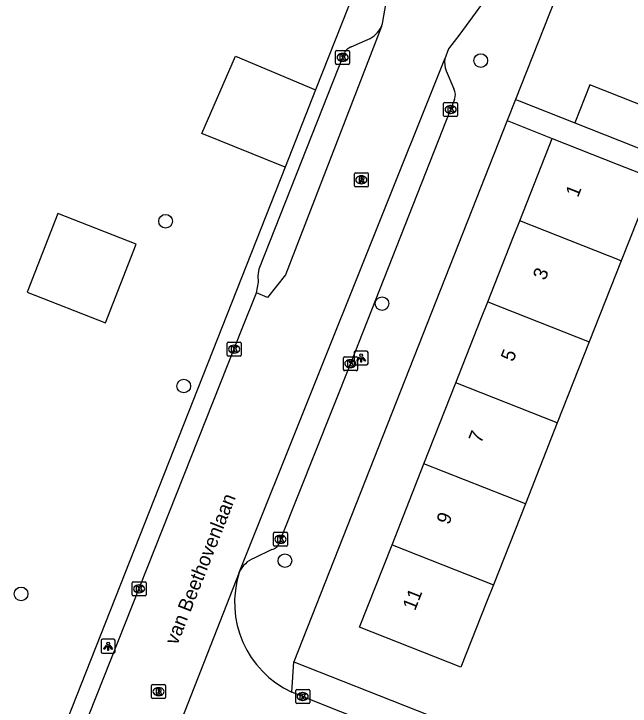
# Model space of a CAD drawing. Extents: x 159822 to 160765, y 380693 to 381634.
# Drawn here: x 160308.25 to 160352.4, y 381326.15 to 381375.72 of the extents above; entities that cross this region are included whole.
import ezdxf

# ---------------------------------------------------------------- set-up
doc = ezdxf.new("R2010")
doc.units = 0
for name, color, linetype in [('IMGEO_Boom', 7, 'Continuous'), ('IMGEO_Groenvoorziening', 7, 'Continuous'), ('IMGEO_Kolk', 7, 'Continuous'), ('IMGEO_Lichtpunt', 7, 'Continuous'), ('IMGEO_Openbare_ruimte_label', 7, 'Continuous'), ('IMGEO_Pand', 7, 'Continuous'), ('IMGEO_Pand_nummerreeks', 7, 'Continuous'), ('IMGEO_Rijbaan_lokaal_open', 7, 'Continuous'), ('IMGEO_Rioolput', 7, 'Continuous'), ('IMGEO_Voetpad_open', 7, 'Continuous')]:
    doc.layers.add(name, color=color, linetype=linetype)

msp = doc.modelspace()

# ---------------------------------------------------------------- linework, layer by layer
at = {"layer": 'IMGEO_Boom'}
for centre in [(160341.698, 381372.378), (160319.125, 381360.871), (160334.627, 381354.969), (160320.428, 381349.072), (160327.669, 381336.566), (160308.778, 381334.183)]:
    msp.add_circle(centre, 0.489, dxfattribs=at)
at = {"layer": 'IMGEO_Groenvoorziening'}
for points in [[(160327.681, 381364.751), (160321.709, 381367.163), (160324.123, 381372.682), (160329.863, 381370.275)], [(160317.018, 381359.223), (160311.413, 381361.421), (160309.209, 381355.803), (160314.814, 381353.604), (160317.018, 381359.223)]]:
    msp.add_lwpolyline(points, dxfattribs=at)
at = {"layer": 'IMGEO_Kolk'}
for p, q in [((160331.378, 381373.104), (160332.23, 381373.104)), ((160331.303, 381372.178), (160331.303, 381373.03)), ((160331.791, 381372.884), (160331.816, 381372.884)), ((160332.304, 381373.03), (160332.304, 381372.178)), ((160332.23, 381372.104), (160331.378, 381372.104)), ((160331.814, 381372.324), (160331.789, 381372.324)), ((160339.041, 381368.445), (160339.041, 381369.297)), ((160339.116, 381369.371), (160339.968, 381369.371)), ((160339.529, 381369.151), (160339.554, 381369.151)), ((160340.042, 381369.297), (160340.042, 381368.445)), ((160339.968, 381368.371), (160339.116, 381368.371)), ((160339.552, 381368.591), (160339.527, 381368.591)), ((160323.536, 381351.281), (160323.536, 381352.133)), ((160323.611, 381352.207), (160324.463, 381352.207)), ((160324.024, 381351.987), (160324.049, 381351.987)), ((160324.537, 381352.133), (160324.537, 381351.281)), ((160324.047, 381351.427), (160324.022, 381351.427)), ((160324.463, 381351.207), (160323.611, 381351.207)), ((160331.859, 381350.245), (160331.859, 381351.097)), ((160331.934, 381351.171), (160332.786, 381351.171)), ((160332.347, 381350.951), (160332.372, 381350.951)), ((160332.86, 381351.097), (160332.86, 381350.245)), ((160332.37, 381350.391), (160332.345, 381350.391)), ((160332.786, 381350.171), (160331.934, 381350.171)), ((160326.855, 381337.67), (160326.855, 381338.522)), ((160326.93, 381338.596), (160327.782, 381338.596)), ((160327.343, 381338.376), (160327.368, 381338.376)), ((160327.856, 381338.522), (160327.856, 381337.67)), ((160327.782, 381337.596), (160326.93, 381337.596)), ((160327.366, 381337.816), (160327.341, 381337.816)), ((160316.727, 381334.121), (160316.727, 381334.973)), ((160316.802, 381335.047), (160317.654, 381335.047)), ((160317.728, 381334.973), (160317.728, 381334.121)), ((160317.215, 381334.827), (160317.24, 381334.827)), ((160317.654, 381334.047), (160316.802, 381334.047)), ((160317.238, 381334.267), (160317.213, 381334.267)), ((160328.447, 381326.411), (160328.447, 381327.263)), ((160328.522, 381327.337), (160329.374, 381327.337)), ((160328.935, 381327.117), (160328.96, 381327.117)), ((160329.448, 381327.263), (160329.448, 381326.411)), ((160328.958, 381326.557), (160328.933, 381326.557)), ((160329.374, 381326.337), (160328.522, 381326.337))]:
    msp.add_line(p, q, dxfattribs=at)
for points in [[(160331.378, 381373.104), (160332.23, 381373.104)], [(160331.303, 381372.178), (160331.303, 381373.03)], [(160331.624, 381372.804), (160331.747, 381372.804), (160331.747, 381372.653), (160331.877, 381372.804), (160332.041, 381372.804), (160331.895, 381372.653), (160332.048, 381372.404), (160331.896, 381372.404), (160331.811, 381372.568), (160331.747, 381372.501), (160331.747, 381372.404), (160331.624, 381372.404), (160331.624, 381372.804)], [(160332.304, 381373.03), (160332.304, 381372.178)], [(160332.23, 381372.104), (160331.378, 381372.104)], [(160339.041, 381368.445), (160339.041, 381369.297)], [(160339.116, 381369.371), (160339.968, 381369.371)], [(160340.042, 381369.297), (160340.042, 381368.445)], [(160339.362, 381369.071), (160339.485, 381369.071), (160339.485, 381368.92), (160339.615, 381369.071), (160339.779, 381369.071), (160339.633, 381368.92), (160339.786, 381368.671), (160339.634, 381368.671), (160339.549, 381368.835), (160339.485, 381368.768), (160339.485, 381368.671), (160339.362, 381368.671), (160339.362, 381369.071)], [(160339.968, 381368.371), (160339.116, 381368.371)], [(160323.536, 381351.281), (160323.536, 381352.133)], [(160323.611, 381352.207), (160324.463, 381352.207)], [(160323.857, 381351.907), (160323.98, 381351.907), (160323.98, 381351.756), (160324.11, 381351.907), (160324.274, 381351.907), (160324.128, 381351.756), (160324.281, 381351.507), (160324.129, 381351.507), (160324.044, 381351.671), (160323.98, 381351.604), (160323.98, 381351.507), (160323.857, 381351.507), (160323.857, 381351.907)], [(160324.537, 381352.133), (160324.537, 381351.281)], [(160324.463, 381351.207), (160323.611, 381351.207)], [(160331.859, 381350.245), (160331.859, 381351.097)], [(160331.934, 381351.171), (160332.786, 381351.171)], [(160332.18, 381350.871), (160332.303, 381350.871), (160332.303, 381350.72), (160332.433, 381350.871), (160332.597, 381350.871), (160332.451, 381350.72), (160332.604, 381350.471), (160332.452, 381350.471), (160332.367, 381350.635), (160332.303, 381350.568), (160332.303, 381350.471), (160332.18, 381350.471), (160332.18, 381350.871)], [(160332.86, 381351.097), (160332.86, 381350.245)], [(160332.786, 381350.171), (160331.934, 381350.171)], [(160326.855, 381337.67), (160326.855, 381338.522)], [(160326.93, 381338.596), (160327.782, 381338.596)], [(160327.856, 381338.522), (160327.856, 381337.67)], [(160327.176, 381338.296), (160327.299, 381338.296), (160327.299, 381338.145), (160327.429, 381338.296), (160327.593, 381338.296), (160327.447, 381338.145), (160327.6, 381337.896), (160327.448, 381337.896), (160327.363, 381338.06), (160327.299, 381337.993), (160327.299, 381337.896), (160327.176, 381337.896), (160327.176, 381338.296)], [(160327.782, 381337.596), (160326.93, 381337.596)], [(160316.727, 381334.121), (160316.727, 381334.973)], [(160316.802, 381335.047), (160317.654, 381335.047)], [(160317.728, 381334.973), (160317.728, 381334.121)], [(160317.048, 381334.747), (160317.171, 381334.747), (160317.171, 381334.596), (160317.301, 381334.747), (160317.465, 381334.747), (160317.319, 381334.596), (160317.472, 381334.347), (160317.32, 381334.347), (160317.235, 381334.511), (160317.171, 381334.444), (160317.171, 381334.347), (160317.048, 381334.347), (160317.048, 381334.747)], [(160317.654, 381334.047), (160316.802, 381334.047)], [(160328.447, 381326.411), (160328.447, 381327.263)], [(160328.522, 381327.337), (160329.374, 381327.337)], [(160328.768, 381327.037), (160328.891, 381327.037), (160328.891, 381326.886), (160329.021, 381327.037), (160329.185, 381327.037), (160329.039, 381326.886), (160329.192, 381326.637), (160329.04, 381326.637), (160328.955, 381326.801), (160328.891, 381326.734), (160328.891, 381326.637), (160328.768, 381326.637), (160328.768, 381327.037)], [(160329.448, 381327.263), (160329.448, 381326.411)], [(160329.374, 381326.337), (160328.522, 381326.337)]]:
    msp.add_lwpolyline(points, dxfattribs=at)
for centre, start, end in [((160331.38, 381373.028), 91.552, 178.448), ((160331.38, 381373.028), 91.552, 178.448), ((160332.228, 381373.028), 1.552, 88.448), ((160332.228, 381373.028), 1.552, 88.448), ((160331.38, 381372.18), 181.552, 268.448), ((160331.38, 381372.18), 181.552, 268.448), ((160332.228, 381372.18), 271.552, 358.448), ((160332.228, 381372.18), 271.552, 358.448), ((160339.118, 381369.295), 91.552, 178.448), ((160339.118, 381369.295), 91.552, 178.448), ((160339.966, 381369.295), 1.552, 88.448), ((160339.966, 381369.295), 1.552, 88.448), ((160339.118, 381368.447), 181.552, 268.448), ((160339.118, 381368.447), 181.552, 268.448), ((160339.966, 381368.447), 271.552, 358.448), ((160339.966, 381368.447), 271.552, 358.448), ((160323.613, 381352.131), 91.552, 178.448), ((160323.613, 381352.131), 91.552, 178.448), ((160324.461, 381352.131), 1.552, 88.448), ((160324.461, 381352.131), 1.552, 88.448), ((160323.613, 381351.283), 181.552, 268.448), ((160323.613, 381351.283), 181.552, 268.448), ((160324.461, 381351.283), 271.552, 358.448), ((160324.461, 381351.283), 271.552, 358.448), ((160331.936, 381351.095), 91.552, 178.448), ((160331.936, 381351.095), 91.552, 178.448), ((160332.784, 381351.095), 1.552, 88.448), ((160332.784, 381351.095), 1.552, 88.448), ((160331.936, 381350.247), 181.552, 268.448), ((160331.936, 381350.247), 181.552, 268.448), ((160332.784, 381350.247), 271.552, 358.448), ((160332.784, 381350.247), 271.552, 358.448), ((160326.932, 381338.52), 91.552, 178.448), ((160326.932, 381338.52), 91.552, 178.448), ((160327.78, 381338.52), 1.552, 88.448), ((160327.78, 381338.52), 1.552, 88.448), ((160326.932, 381337.672), 181.552, 268.448), ((160326.932, 381337.672), 181.552, 268.448), ((160327.78, 381337.672), 271.552, 358.448), ((160327.78, 381337.672), 271.552, 358.448), ((160316.804, 381334.971), 91.552, 178.448), ((160316.804, 381334.971), 91.552, 178.448), ((160317.652, 381334.971), 1.552, 88.448), ((160317.652, 381334.971), 1.552, 88.448), ((160316.804, 381334.123), 181.552, 268.448), ((160316.804, 381334.123), 181.552, 268.448), ((160317.652, 381334.123), 271.552, 358.448), ((160317.652, 381334.123), 271.552, 358.448), ((160328.524, 381327.261), 91.552, 178.448), ((160328.524, 381327.261), 91.552, 178.448), ((160329.372, 381327.261), 1.552, 88.448), ((160329.372, 381327.261), 1.552, 88.448), ((160328.524, 381326.413), 181.552, 268.448), ((160328.524, 381326.413), 181.552, 268.448), ((160329.372, 381326.413), 271.552, 358.448), ((160329.372, 381326.413), 271.552, 358.448)]:
    msp.add_arc(centre, 0.0765, start, end, dxfattribs=at)
for centre, major_axis, ratio, start_param, end_param in [((160331.79, 381372.604), (-0.387, 0.002), 0.722429, 4.712389, 7.853982), ((160331.815, 381372.604), (-0.39, 0.002), 0.717154, 1.570796, 4.712389), ((160339.528, 381368.871), (-0.387, 0.002), 0.722429, 4.712389, 7.853982), ((160339.553, 381368.871), (-0.39, 0.002), 0.717154, 1.570796, 4.712389), ((160324.023, 381351.707), (-0.387, 0.002), 0.722429, 4.712389, 7.853982), ((160324.048, 381351.707), (-0.39, 0.002), 0.717154, 1.570796, 4.712389), ((160332.346, 381350.671), (-0.387, 0.002), 0.722429, 4.712389, 7.853982), ((160332.371, 381350.671), (-0.39, 0.002), 0.717154, 1.570796, 4.712389), ((160327.342, 381338.096), (-0.387, 0.002), 0.722429, 4.712389, 7.853982), ((160327.367, 381338.096), (-0.39, 0.002), 0.717154, 1.570796, 4.712389), ((160317.214, 381334.547), (-0.387, 0.002), 0.722429, 4.712389, 7.853982), ((160317.239, 381334.547), (-0.39, 0.002), 0.717154, 1.570796, 4.712389), ((160328.934, 381326.837), (-0.387, 0.002), 0.722429, 4.712389, 7.853982), ((160328.959, 381326.837), (-0.39, 0.002), 0.717154, 1.570796, 4.712389)]:
    msp.add_ellipse(centre, major_axis=major_axis, ratio=ratio, start_param=start_param, end_param=end_param, dxfattribs=at)
at = {"layer": 'IMGEO_Lichtpunt'}
for p, q in [((160332.628, 381351.48), (160332.628, 381350.673)), ((160332.628, 381351.48), (160332.628, 381350.673)), ((160333.53, 381351.575), (160332.722, 381351.575)), ((160333.53, 381351.575), (160332.722, 381351.575)), ((160333.624, 381350.673), (160333.624, 381351.48)), ((160333.624, 381350.673), (160333.624, 381351.48)), ((160332.722, 381350.579), (160333.53, 381350.579)), ((160332.722, 381350.579), (160333.53, 381350.579)), ((160315.41, 381330.938), (160314.602, 381330.938)), ((160315.41, 381330.938), (160314.602, 381330.938)), ((160314.508, 381330.843), (160314.508, 381330.036)), ((160314.508, 381330.843), (160314.508, 381330.036)), ((160315.504, 381330.036), (160315.504, 381330.843)), ((160315.504, 381330.036), (160315.504, 381330.843)), ((160314.602, 381329.942), (160315.41, 381329.942)), ((160314.602, 381329.942), (160315.41, 381329.942))]:
    msp.add_line(p, q, dxfattribs=at)
for points in [[(160333.002, 381351.144), (160333.041, 381351.116), (160332.853, 381350.854), (160332.815, 381350.881), (160333.002, 381351.144)], [(160333.104, 381351.096), (160333.151, 381351.096), (160333.151, 381350.774), (160333.104, 381350.774), (160333.104, 381351.096)], [(160333.214, 381351.116), (160333.252, 381351.143), (160333.439, 381350.881), (160333.4, 381350.853), (160333.214, 381351.116)], [(160314.882, 381330.507), (160314.921, 381330.479), (160314.733, 381330.217), (160314.695, 381330.244), (160314.882, 381330.507)], [(160314.984, 381330.459), (160315.031, 381330.459), (160315.031, 381330.137), (160314.984, 381330.137), (160314.984, 381330.459)], [(160315.094, 381330.479), (160315.132, 381330.506), (160315.319, 381330.244), (160315.28, 381330.216), (160315.094, 381330.479)]]:
    msp.add_lwpolyline(points, dxfattribs=at)
for centre in [(160333.127, 381351.278), (160315.007, 381330.641)]:
    msp.add_circle(centre, 0.0994, dxfattribs=at)
for centre, start, end in [((160332.722, 381351.48), 90, 180), ((160332.722, 381351.48), 90, 180), ((160333.53, 381351.48), 0, 90), ((160333.53, 381351.48), 0, 90), ((160332.722, 381350.673), 180, 270), ((160332.722, 381350.673), 180, 270), ((160333.53, 381350.673), 270, 0), ((160333.53, 381350.673), 270, 360), ((160314.602, 381330.843), 90, 180), ((160314.602, 381330.843), 90, 180), ((160315.41, 381330.843), 0, 90), ((160315.41, 381330.843), 0, 90), ((160314.602, 381330.036), 180, 270), ((160314.602, 381330.036), 180, 270), ((160315.41, 381330.036), 270, 0), ((160315.41, 381330.036), 270, 360)]:
    msp.add_arc(centre, 0.0946, start, end, dxfattribs=at)
at = {"layer": 'IMGEO_Pand'}
for points in [[(160354.051, 381365.707), (160355.121, 381368.421), (160352.707, 381369.373), (160349.51, 381370.633), (160348.44, 381367.919)], [(160348.44, 381367.919), (160351.637, 381366.659), (160354.051, 381365.707)], [(160344.492, 381360.891), (160346.823, 381366.8)], [(160346.823, 381366.8), (160351.475, 381364.966), (160354.086, 381363.936)], [(160354.086, 381363.936), (160351.755, 381358.026)], [(160342.206, 381355.094), (160344.003, 381359.651), (160344.492, 381360.891)], [(160351.755, 381358.026), (160344.492, 381360.891)], [(160351.755, 381358.026), (160349.468, 381352.229)], [(160339.92, 381349.298), (160341.716, 381353.853), (160342.206, 381355.094)], [(160342.206, 381355.094), (160349.468, 381352.229)], [(160349.468, 381352.229), (160347.182, 381346.432)], [(160337.633, 381343.501), (160339.92, 381349.298)], [(160347.182, 381346.432), (160339.92, 381349.298)], [(160347.182, 381346.432), (160344.895, 381340.635)], [(160335.347, 381337.705), (160337.633, 381343.501)], [(160344.895, 381340.635), (160337.633, 381343.501)], [(160344.895, 381340.635), (160342.609, 381334.838)], [(160342.609, 381334.838), (160342.114, 381333.583), (160340.279, 381328.931), (160333.016, 381331.796), (160335.347, 381337.705)], [(160335.347, 381337.705), (160342.609, 381334.838)]]:
    msp.add_lwpolyline(points, dxfattribs=at)
at = {"layer": 'IMGEO_Rijbaan_lokaal_open'}
for points in [[(160334.58, 381374.806), (160334.664, 381375.02), (160335.694, 381380.931), (160335.886, 381381.655), (160336.806, 381383.995), (160337.727, 381386.312), (160338.069, 381386.973), (160341.463, 381391.931)], [(160346.086, 381390.314), (160345.23, 381383.344), (160343.412, 381378.689), (160342.853, 381377.914), (160340.19, 381374.267), (160339.393, 381373.215), (160339.132, 381372.508)], [(160334.58, 381374.806), (160327.725, 381357.024), (160326.426, 381355.415), (160325.632, 381355.733)], [(160324.406, 381335.726), (160339.132, 381372.508)], [(160311.054, 381318.986), (160324.621, 381353.178), (160325.632, 381355.733)], [(160324.406, 381335.726), (160317.046, 381316.965), (160316.946, 381316.648)], [(160341.019, 381322.049), (160330.297, 381326.294), (160328.162, 381327.153)]]:
    msp.add_lwpolyline(points, dxfattribs=at)
msp.add_arc((160331.129, 381333.562), 7.063, 162.1595, 245.1589, dxfattribs=at)
at = {"layer": 'IMGEO_Rioolput'}
for p, q in [((160332.646, 381363.414), (160332.646, 381364.266)), ((160332.721, 381364.34), (160333.573, 381364.34)), ((160333.647, 381364.266), (160333.647, 381363.414)), ((160333.134, 381364.12), (160333.159, 381364.12)), ((160333.573, 381363.34), (160332.721, 381363.34)), ((160333.157, 381363.56), (160333.132, 381363.56)), ((160318.121, 381326.764), (160318.121, 381327.616)), ((160318.196, 381327.69), (160319.048, 381327.69)), ((160318.609, 381327.47), (160318.634, 381327.47)), ((160319.122, 381327.616), (160319.122, 381326.764)), ((160319.048, 381326.69), (160318.196, 381326.69)), ((160318.632, 381326.91), (160318.607, 381326.91))]:
    msp.add_line(p, q, dxfattribs=at)
for points in [[(160332.646, 381363.414), (160332.646, 381364.266)], [(160332.721, 381364.34), (160333.573, 381364.34)], [(160333.647, 381364.266), (160333.647, 381363.414)], [(160333.235, 381364.038), (160332.983, 381364.04), (160332.983, 381363.64)], [(160332.983, 381363.64), (160333.107, 381363.64), (160333.107, 381363.802), (160333.118, 381363.802)], [(160333.161, 381363.959), (160333.107, 381363.959), (160333.107, 381363.878)], [(160333.107, 381363.878), (160333.159, 381363.878)], [(160333.165, 381363.773), (160333.236, 381363.64), (160333.376, 381363.64), (160333.311, 381363.766)], [(160333.573, 381363.34), (160332.721, 381363.34)], [(160318.121, 381326.764), (160318.121, 381327.616)], [(160318.196, 381327.69), (160319.048, 381327.69)], [(160319.122, 381327.616), (160319.122, 381326.764)], [(160318.71, 381327.388), (160318.458, 381327.39), (160318.458, 381326.99)], [(160318.458, 381326.99), (160318.582, 381326.99), (160318.582, 381327.152), (160318.593, 381327.152)], [(160318.636, 381327.309), (160318.582, 381327.309), (160318.582, 381327.228)], [(160318.582, 381327.228), (160318.634, 381327.228)], [(160318.64, 381327.123), (160318.711, 381326.99), (160318.851, 381326.99), (160318.786, 381327.116)], [(160319.048, 381326.69), (160318.196, 381326.69)]]:
    msp.add_lwpolyline(points, dxfattribs=at)
for centre, radius, start, end in [((160332.723, 381364.264), 0.0765, 91.552, 178.448), ((160332.723, 381364.264), 0.0765, 91.552, 178.448), ((160333.571, 381364.264), 0.0765, 1.552, 88.448), ((160333.571, 381364.264), 0.0765, 1.552, 88.448), ((160333.117, 381363.749), 0.0533, 26.0293, 88.6989), ((160333.143, 381364.067), 0.19, 274.7715, 282.9687), ((160333.167, 381363.863), 0.0964, 77.0061, 93.1865), ((160333.181, 381363.92), 0.0378, 276.6634, 79.6772), ((160333.234, 381363.928), 0.109, 350.3612, 89.416), ((160333.232, 381363.928), 0.112, 277.5842, 350.9817), ((160333.216, 381363.713), 0.108, 29.5134, 73.7905), ((160332.723, 381363.416), 0.0765, 181.552, 268.448), ((160332.723, 381363.416), 0.0765, 181.552, 268.448), ((160333.571, 381363.416), 0.0765, 271.552, 358.448), ((160333.571, 381363.416), 0.0765, 271.552, 358.448), ((160318.198, 381327.614), 0.0765, 91.552, 178.448), ((160318.198, 381327.614), 0.0765, 91.552, 178.448), ((160319.046, 381327.614), 0.0765, 1.552, 88.448), ((160319.046, 381327.614), 0.0765, 1.552, 88.448), ((160318.592, 381327.099), 0.0533, 26.0293, 88.6989), ((160318.618, 381327.417), 0.19, 274.7715, 282.9687), ((160318.642, 381327.213), 0.0964, 77.0061, 93.1865), ((160318.656, 381327.27), 0.0378, 276.6634, 79.6772), ((160318.709, 381327.278), 0.109, 350.3612, 89.416), ((160318.707, 381327.278), 0.112, 277.5842, 350.9817), ((160318.691, 381327.063), 0.108, 29.5134, 73.7905), ((160318.198, 381326.766), 0.0765, 181.552, 268.448), ((160318.198, 381326.766), 0.0765, 181.552, 268.448), ((160319.046, 381326.766), 0.0765, 271.552, 358.448), ((160319.046, 381326.766), 0.0765, 271.552, 358.448)]:
    msp.add_arc(centre, radius, start, end, dxfattribs=at)
for centre, major_axis, ratio, start_param, end_param in [((160333.133, 381363.84), (-0.387, 0.002), 0.722429, 4.712389, 7.853982), ((160333.158, 381363.84), (-0.39, 0.002), 0.717154, 1.570796, 4.712389), ((160318.608, 381327.19), (-0.387, 0.002), 0.722429, 4.712389, 7.853982), ((160318.633, 381327.19), (-0.39, 0.002), 0.717154, 1.570796, 4.712389)]:
    msp.add_ellipse(centre, major_axis=major_axis, ratio=ratio, start_param=start_param, end_param=end_param, dxfattribs=at)
at = {"layer": 'IMGEO_Voetpad_open'}
for points in [[(160353.609, 381393.461), (160344.195, 381369.593)], [(160335.491, 381384.517), (160329.863, 381370.275)], [(160332.42, 381373.359), (160333.623, 381373.887)], [(160325.632, 381355.733), (160325.775, 381356.504), (160325.752, 381356.962), (160325.818, 381357.454), (160331.894, 381372.811)], [(160339.213, 381371.629), (160339.763, 381370.354)], [(160329.863, 381370.275), (160327.681, 381364.751)], [(160339.82, 381369.585), (160339.541, 381368.872), (160332.358, 381350.672), (160327.355, 381338.096), (160327.295, 381337.879)], [(160344.195, 381369.593), (160343.595, 381368.072)], [(160344.195, 381369.593), (160344.446, 381369.494), (160348.44, 381367.919)], [(160343.595, 381368.072), (160328.314, 381329.328)], [(160343.595, 381368.072), (160346.823, 381366.8)], [(160327.681, 381364.751), (160306.429, 381310.967)], [(160326.728, 381337.355), (160325.476, 381336.753)], [(160328.162, 381327.153), (160328.314, 381329.328)], [(160328.314, 381329.328), (160354.702, 381318.907)]]:
    msp.add_lwpolyline(points, dxfattribs=at)
for centre, radius, start, end in [((160332.913, 381375.584), 1.84, 292.7025, 334.9767), ((160332.714, 381372.551), 0.86, 109.9643, 162.3827), ((160340.952, 381372.233), 1.841, 171.3942, 199.1357), ((160339.029, 381369.913), 0.856, 337.4734, 31.0048), ((160326.552, 381338.115), 0.78, 283.0713, 342.4146), ((160326.156, 381334.974), 1.905, 110.911, 156.7396)]:
    msp.add_arc(centre, radius, start, end, dxfattribs=at)

# ---------------------------------------------------------------- texts
at = {"layer": 'IMGEO_Openbare_ruimte_label'}
msp.add_text('van Beethovenlaan', height=1, rotation=68.4113, dxfattribs=at).set_placement((160319.959, 381330.468))
at = {"layer": 'IMGEO_Pand_nummerreeks'}
for s, p in [('1', (160348.664, 381362.529)), ('3', (160346.321, 381356.589)), ('5', (160344.02, 381350.755)), ('7', (160341.719, 381344.921)), ('9', (160339.417, 381339.087)), ('11', (160336.989, 381332.932))]:
    msp.add_text(s, height=1, rotation=68.4737, dxfattribs=at).set_placement(p)

doc.saveas('drawing.dxf')
